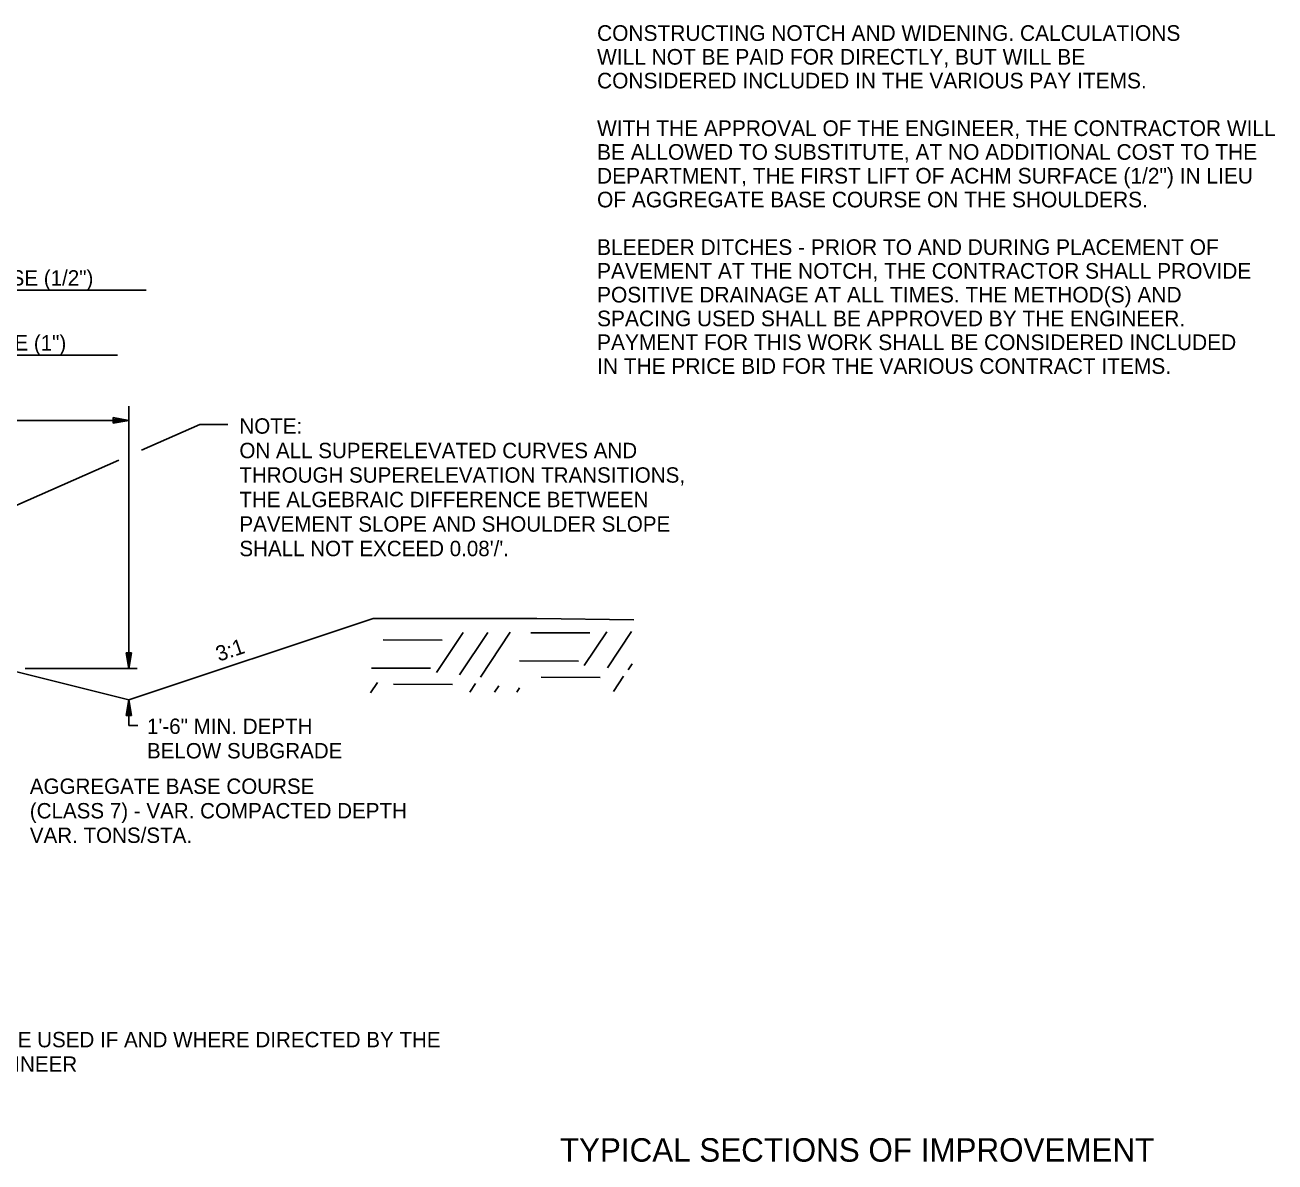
# Model space of a CAD drawing. Extents: x 1398183 to 1398373, y 1967240 to 1968889.
# Drawn here: x 1398287.69 to 1398335.64, y 1968326.36 to 1968369.98 of the extents above; entities that cross this region are included whole.
import ezdxf

# ---------------------------------------------------------------- set-up
doc = ezdxf.new("R2010")
doc.units = 0
for name, color, linetype in [('10', 7, 'Continuous'), ('19', 7, 'Continuous'), ('42', 7, 'Continuous'), ('60', 7, 'Continuous'), ('9', 7, 'Continuous'), ('Default', 7, 'Continuous')]:
    doc.layers.add(name, color=color, linetype=linetype)

msp = doc.modelspace()

# ---------------------------------------------------------------- linework, layer by layer
at = {"layer": '19'}
for p, q in [((1398261.673, 1968359.811), (1398292.34, 1968359.811)), ((1398237.673, 1968357.311), (1398291.239, 1968357.311)), ((1398291.672, 1968345.294), (1398291.672, 1968355.358)), ((1398291.073, 1968354.916), (1398291.073, 1968354.706)), ((1398291.673, 1968354.811), (1398291.073, 1968354.916)), ((1398291.513, 1968354.826), (1398291.073, 1968354.861)), ((1398289.673, 1968354.811), (1398273.673, 1968354.811)), ((1398291.673, 1968354.811), (1398273.673, 1968354.811)), ((1398291.073, 1968354.706), (1398291.673, 1968354.811)), ((1398291.073, 1968354.756), (1398291.513, 1968354.796)), ((1398291.286, 1968353.284), (1398287.376, 1968351.563)), ((1398291.672, 1968344.089), (1398301.04, 1968347.211)), ((1398279.673, 1968347.089), (1398291.672, 1968344.089)), ((1398291.777, 1968345.894), (1398291.567, 1968345.894)), ((1398291.567, 1968345.894), (1398291.672, 1968345.294)), ((1398291.617, 1968345.894), (1398291.657, 1968345.454)), ((1398291.672, 1968345.294), (1398291.777, 1968345.894)), ((1398291.687, 1968345.454), (1398291.722, 1968345.894)), ((1398291.673, 1968344.087), (1398291.568, 1968343.487)), ((1398291.658, 1968343.927), (1398291.623, 1968343.487)), ((1398291.778, 1968343.487), (1398291.673, 1968344.087)), ((1398291.728, 1968343.487), (1398291.688, 1968343.927)), ((1398291.568, 1968343.487), (1398291.778, 1968343.487))]:
    msp.add_line(p, q, dxfattribs=at)
msp.add_lwpolyline([(1398295.465, 1968354.651), (1398294.391, 1968354.651), (1398292.152, 1968353.665)], dxfattribs=at)
at = {"layer": '42'}
msp.add_lwpolyline([(1398301.04, 1968347.211), (1398307.325, 1968347.211), (1398311.041, 1968347.161)], dxfattribs=at)
at = {"layer": '9'}
for p, q in [((1398304.494, 1968346.673), (1398303.471, 1968345.139)), ((1398305.447, 1968346.678), (1398304.362, 1968345.051)), ((1398306.306, 1968346.683), (1398305.16, 1968344.963)), ((1398310.005, 1968346.704), (1398309.143, 1968345.412)), ((1398310.957, 1968346.709), (1398310.034, 1968345.324)), ((1398303.687, 1968346.383), (1398301.425, 1968346.389)), ((1398309.359, 1968346.656), (1398307.097, 1968346.662)), ((1398303.248, 1968345.305), (1398300.986, 1968345.311)), ((1398308.92, 1968345.578), (1398306.658, 1968345.583)), ((1398310.985, 1968345.467), (1398310.831, 1968345.236)), ((1398301.212, 1968344.755), (1398300.947, 1968344.359)), ((1398309.758, 1968344.952), (1398307.496, 1968344.957)), ((1398310.647, 1968344.994), (1398310.259, 1968344.411)), ((1398304.086, 1968344.679), (1398301.824, 1968344.685)), ((1398304.976, 1968344.721), (1398304.749, 1968344.38)), ((1398305.866, 1968344.633), (1398305.701, 1968344.386)), ((1398306.664, 1968344.545), (1398306.561, 1968344.39))]:
    msp.add_line(p, q, dxfattribs=at)
at = {"layer": 'Default'}
msp.add_line((1398291.986, 1968345.293), (1398287.701, 1968345.293), dxfattribs=at)
msp.add_lwpolyline([(1398291.673, 1968344.087), (1398291.673, 1968343.107), (1398292.015, 1968343.107)], dxfattribs=at)

# ---------------------------------------------------------------- texts
at = {"layer": '10'}
for s, height, rotation, p in [('3:1', 0.59, 18.4349, (1398295.125, 1968345.55)), ('1\'-6" MIN. DEPTH', 0.59001, 360, (1398292.367, 1968342.782)), ('BELOW SUBGRADE', 0.59001, 360, (1398292.367, 1968341.842)), ('TO BE USED IF AND WHERE DIRECTED BY THE ', 0.59001, 360, (1398285.569, 1968330.759)), ('ENGINEER', 0.59, 360, (1398285.569, 1968329.819))]:
    msp.add_text(s, height=height, rotation=rotation, dxfattribs=at).set_placement(p)
at = {"layer": '19'}
for s, height, p in [('CONSTRUCTING NOTCH AND WIDENING. CALCULATIONS', 0.6, (1398309.634, 1968369.372)), ('WILL NOT BE PAID FOR DIRECTLY, BUT WILL BE', 0.6, (1398309.634, 1968368.459)), ('CONSIDERED INCLUDED IN THE VARIOUS PAY ITEMS.', 0.6, (1398309.634, 1968367.547)), ('WITH THE APPROVAL OF THE ENGINEER, THE CONTRACTOR WILL', 0.6, (1398309.634, 1968365.722)), ('BE ALLOWED TO SUBSTITUTE, AT NO ADDITIONAL COST TO THE', 0.6, (1398309.634, 1968364.809)), ('DEPARTMENT, THE FIRST LIFT OF ACHM SURFACE (1/2") IN LIEU', 0.6, (1398309.634, 1968363.897)), ('OF AGGREGATE BASE COURSE ON THE SHOULDERS.', 0.6, (1398309.634, 1968362.984)), ('BLEEDER DITCHES - PRIOR TO AND DURING PLACEMENT OF', 0.6, (1398309.634, 1968361.159)), ('PAVEMENT AT THE NOTCH, THE CONTRACTOR SHALL PROVIDE', 0.6, (1398309.634, 1968360.247)), ('POSITIVE DRAINAGE AT ALL TIMES. THE METHOD(S) AND', 0.6, (1398309.634, 1968359.334)), ('SPACING USED SHALL BE APPROVED BY THE ENGINEER.', 0.6, (1398309.634, 1968358.422)), ('PAYMENT FOR THIS WORK SHALL BE CONSIDERED INCLUDED', 0.6, (1398309.634, 1968357.509)), ('IN THE PRICE BID FOR THE VARIOUS CONTRACT ITEMS.', 0.6, (1398309.634, 1968356.597)), ('NOTE:', 0.59, (1398295.913, 1968354.301)), ('ON ALL SUPERELEVATED CURVES AND', 0.59001, (1398295.913, 1968353.361)), ('THROUGH SUPERELEVATION TRANSITIONS,', 0.59001, (1398295.913, 1968352.421)), ('THE ALGEBRAIC DIFFERENCE BETWEEN', 0.59001, (1398295.913, 1968351.481)), ('PAVEMENT SLOPE AND SHOULDER SLOPE', 0.59001, (1398295.913, 1968350.541)), ("SHALL NOT EXCEED 0.08'/'.", 0.59001, (1398295.913, 1968349.601))]:
    msp.add_text(s, height=height, dxfattribs=at).set_placement(p)
for s, p in [('AGGREGATE BASE COURSE', (1398287.873, 1968340.48)), ('(CLASS 7) - VAR. COMPACTED DEPTH', (1398287.873, 1968339.54)), ('VAR. TONS/STA.', (1398287.873, 1968338.6))]:
    msp.add_text(s, height=0.59001, rotation=360, dxfattribs=at).set_placement(p)
at = {"layer": '42'}
for s, p in [('12\'-1 1/2" ACHM SURFACE COURSE (1/2")', (1398274.737, 1968359.983)), ('12\'-3 1/8" ACHM BINDER COURSE (1")', (1398275.145, 1968357.492))]:
    msp.add_text(s, height=0.59001, rotation=360, dxfattribs=at).set_placement(p)
at = {"layer": '60'}
msp.add_text('TYPICAL SECTIONS OF IMPROVEMENT', height=0.9, dxfattribs=at).set_placement((1398308.207, 1968326.371))

doc.saveas('drawing.dxf')
